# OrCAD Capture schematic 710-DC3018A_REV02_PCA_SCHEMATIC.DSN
size B; company: ANALOG DEVICES
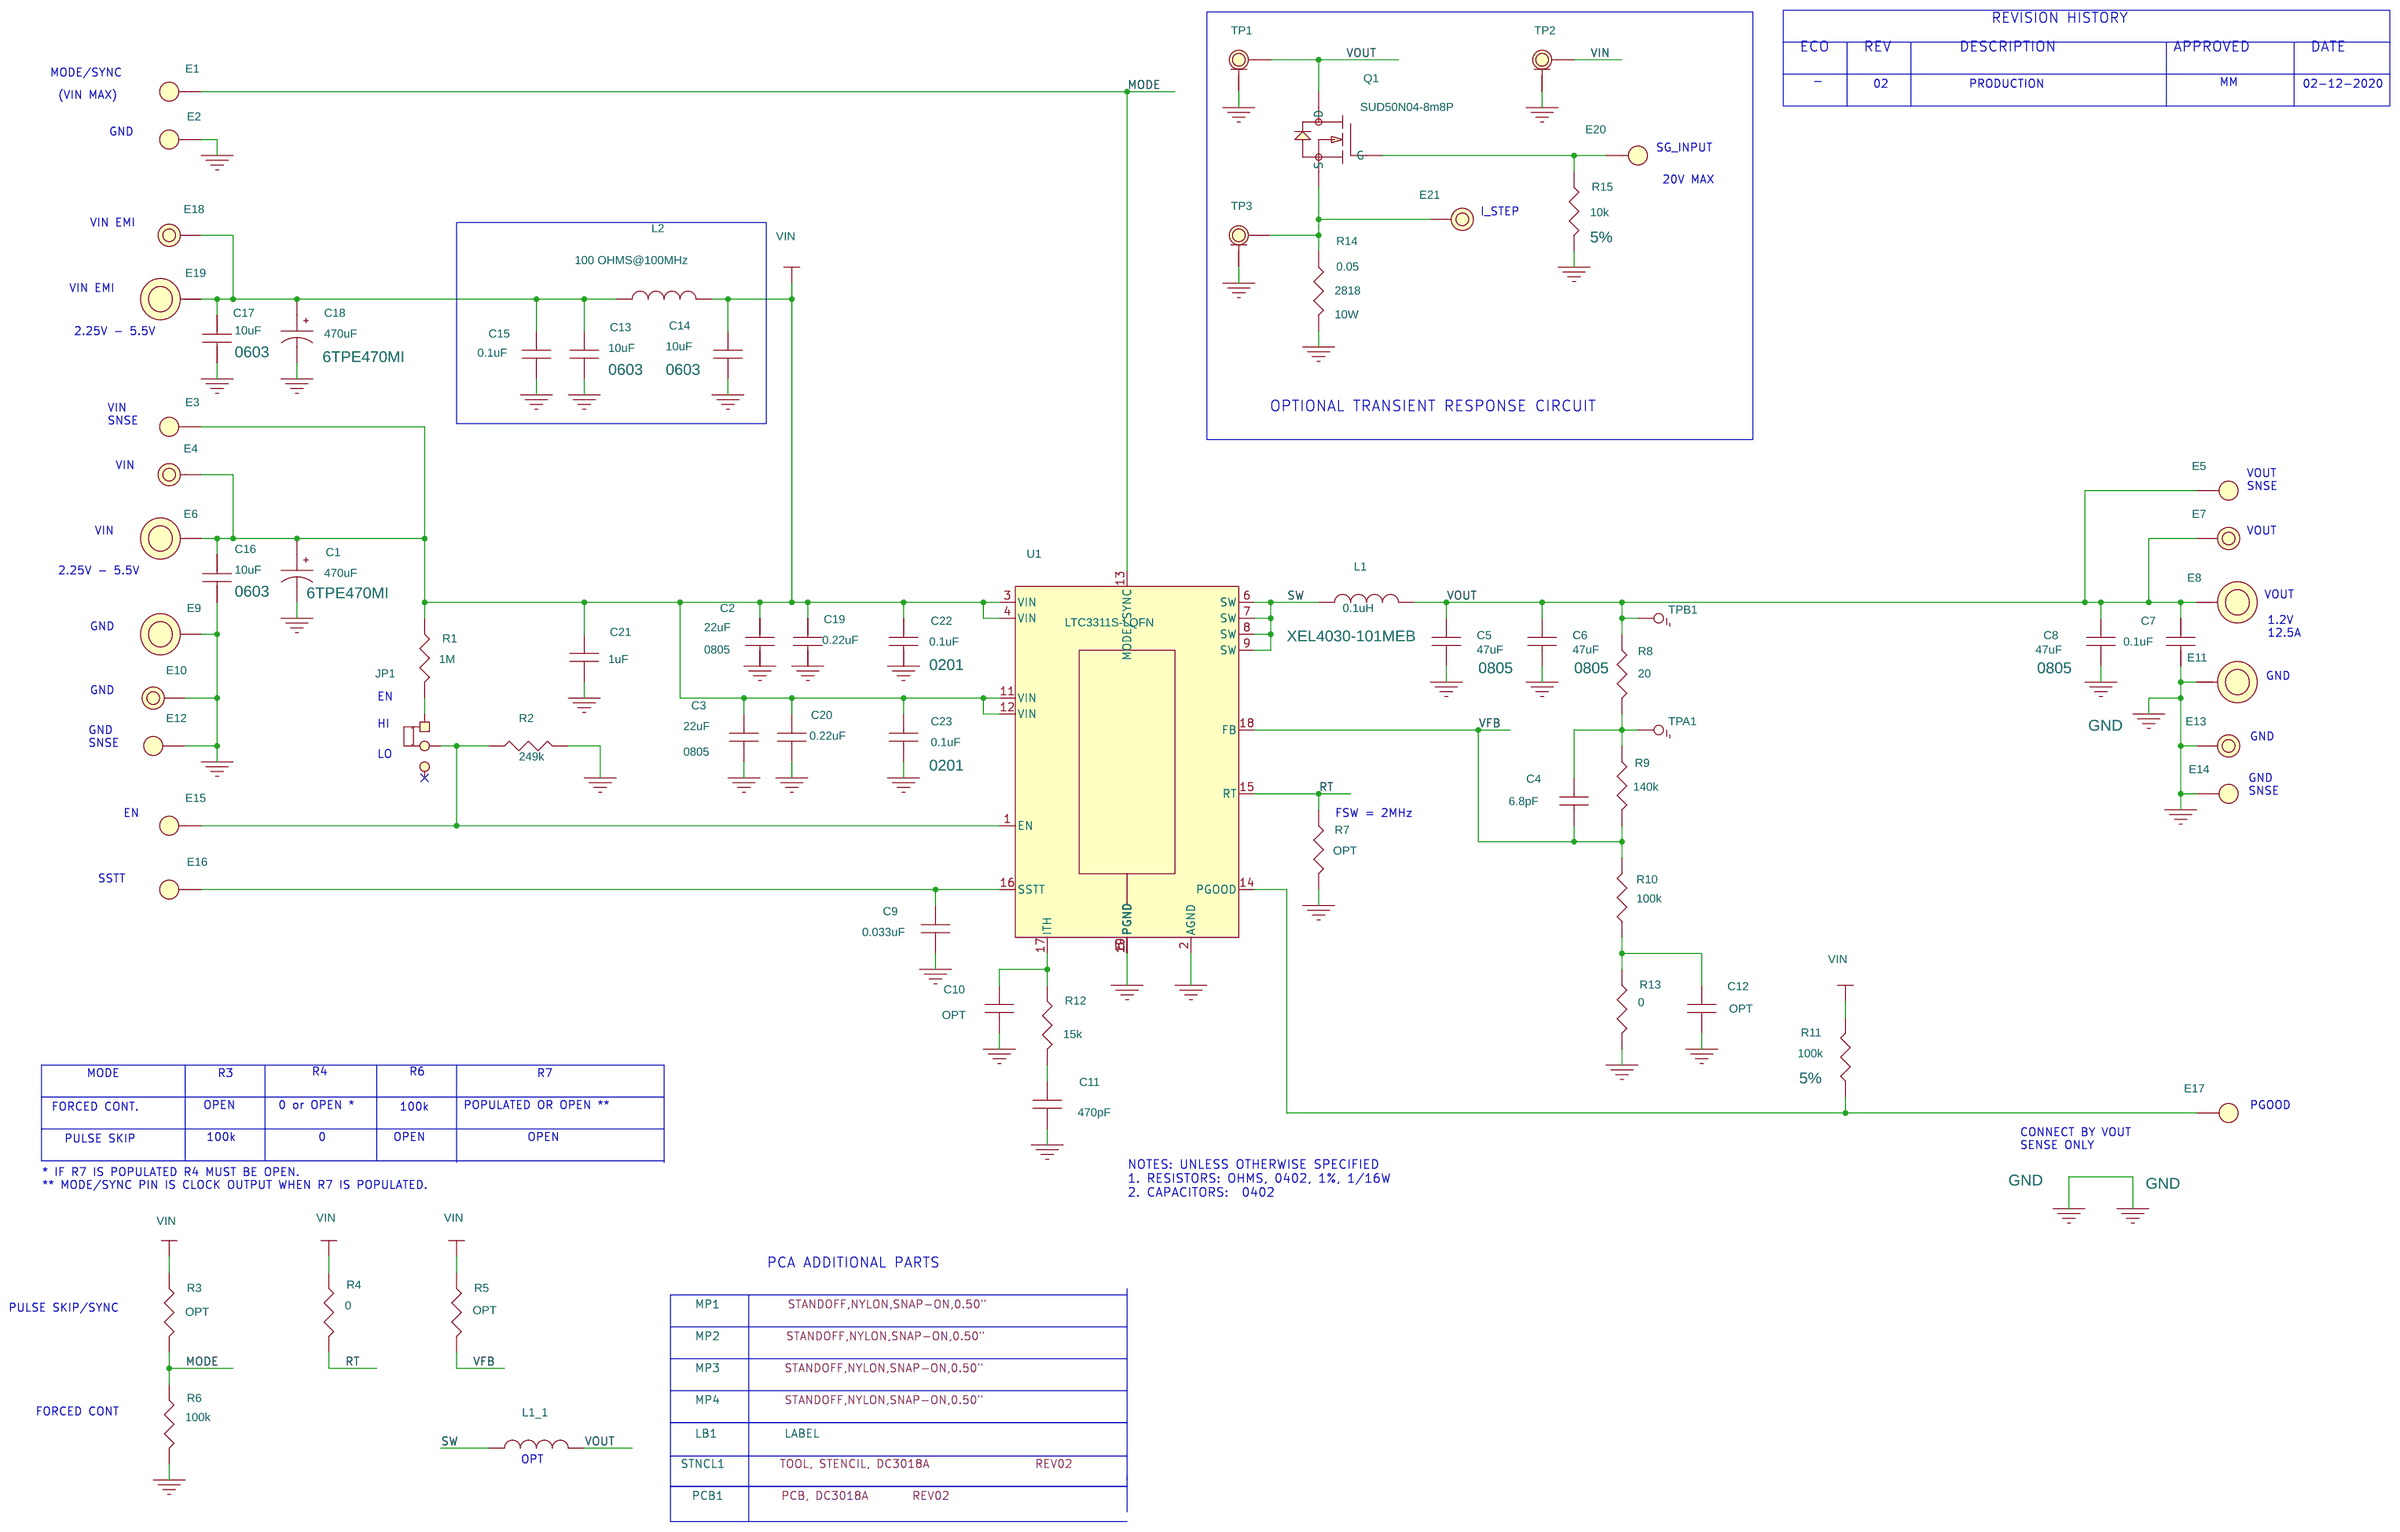
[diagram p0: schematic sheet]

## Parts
C1  470uF  [CAPMP7343N]
C2  22uF  [CC0805N]
C3  22uF  [CC0805N]
C4  6.8pF  [CC0402N]
C5  47uF  [CC0805N]
C6  47uF  [CC0805N]
C7  0.1uF  [CC0402N]
C8  47uF  [CC0805N]
C9  0.033uF  [CC0402N]
C10  OPT  [CC0402N]
C11  470pF  [CC0402N]
C12  OPT  [CC0402N]
C13  10uF  [CC0603N]
C14  10uF  [CC0603N]
C15  0.1uF  [CC0402N]
C16  10uF  [CC0603N]
C17  10uF  [CC0603N]
C18  470uF  [CAPMP7343N]
C19  0.22uF  [CC0402N]
C20  0.22uF  [CC0402N]
C21  1uF  [CC0402N]
C22  0.1uF  [CC0201M]
C23  0.1uF  [CC0201M]
E1  TEST POINT  [MILLMAX2308]
E2  TEST POINT  [MILLMAX2308]
E3  TEST POINT  [MILLMAX2308]
E4  TEST POINT  [MILLMAX2501]
E5  TEST POINT  [MILLMAX2308]
E6  BANANA JACK  [KEY-575-4]
E7  TEST POINT  [MILLMAX2501]
E8  BANANA JACK  [KEY-575-4]
E9  BANANA JACK  [KEY-575-4]
E10  TEST POINT  [MILLMAX2501]
E11  BANANA JACK  [KEY-575-4]
E12  TEST POINT  [MILLMAX2308]
E13  TEST POINT  [MILLMAX2501]
E14  TEST POINT  [MILLMAX2308]
E15  TEST POINT  [MILLMAX2308]
E16  TEST POINT  [MILLMAX2308]
E17  TEST POINT  [MILLMAX2308]
E18  TEST POINT  [MILLMAX2501]
E19  BANANA JACK  [KEY-575-4]
E20  TEST POINT  [MILLMAX2308]
E21  TEST POINT  [MILLMAX2501]
JP1  HDR  [HD1X3-079]
L1  0.1uH  [COILCRAFT-XEL4030]
L1_1  72nH  [COILCRAFT-XEL3515]
L2  100 OHMS@100MHz  [WURTH-74279226101]
LB1  LABEL  [895-0154_REV01]
MP1  STANDOFF  [KEYSTONE_8829-8834]
MP2  STANDOFF  [KEYSTONE_8829-8834]
MP3  STANDOFF  [KEYSTONE_8829-8834]
MP4  STANDOFF  [KEYSTONE_8829-8834]
PCB1  PCB, DC3018A
Q1  SUD50N04-8m8P  [TO-252-3N]
R1  1M  [CR0402N]
R2  249k  [CR0402N]
R3  OPT  [CR0402N]
R4  0  [CR0402N]
R5  OPT  [CR0402N]
R6  100k  [CR0402N]
R7  OPT  [CR0402N]
R8  20  [CR0402N]
R9  140k  [CR0402N]
R10  100k  [CR0402N]
R11  100k  [CR0402N]
R12  15k  [CR0402N]
R13  0  [CR0402N]
R14  0.05  [VISHAY-WSHP2818]
R15  10k  [CR0402N]
STNCL1  TOOL, STENCIL, DC3018A
TP1  TEST JACK  [HODEN-PA-652_ALT1]
TP2  TEST JACK  [HODEN-PA-652_ALT1]
TP3  TEST JACK  [HODEN-PA-652_ALT1]
TPA1  COPPER FEATURE PAD  [PADSTYLE1]
TPB1  COPPER FEATURE PAD  [PADSTYLE1]
U1  LTC3311S-LQFN  [LTC-LQFN-18-1548]
XJP4  SHUNT

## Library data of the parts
C1 C18 = CAP_P_ALT: CAP.,470uF,TANT,POSCAP,6.3V,20%,7343,18mOHMS,TPE; CLASS: DISCRETE; Dielectric Type: TANT,POSCAP; FPLIST: CAPMP7343N,CAPMP7343L,CAPMP7343M; Inventory Qty: 9612; Manufacturer: PANASONIC; Manufacturer PN: 6TPE470MI; PART_NUMBER: 150-0223; Package Size: 7343; Rated Voltage: 6.3V; Tolerance: 20%
C2 C3 = CAP: CAP.,22uF,X5R,25V,20%,0805; CLASS: DISCRETE; Dielectric Type: X5R; FPLIST: CC0805N,CC0805L,CC0805M; Inventory Qty: 12454; Manufacturer: AVX; Manufacturer PN: 08053D226MAT2A; PART_NUMBER: 150-0068; Package Size: 0805; Rated Voltage: 25V; Tolerance: 20%
C4 = CAP: CAP.,6.8pF,C0G,50V,+/-0.25pF,0402; CLASS: DISCRETE; Dielectric Type: C0G; FPLIST: CC0402N,CC0402L,CC0402M; Inventory Qty: 0; Manufacturer: MURATA; Manufacturer PN: GJM1555C1H6R8CB01D; PART_NUMBER: 150-2084; Package Size: 0402; Rated Voltage: 50V; Tolerance: +/-0.25pF
C5 C6 C8 = CAP: CAP.,47uF,X5R,6.3V,20%,0805,AEC-Q200; CLASS: DISCRETE; Dielectric Type: X5R; FPLIST: CC0805N,CC0805L,CC0805M; Inventory Qty: 0; Manufacturer: MURATA; Manufacturer PN: GRT21BR60J476ME13L; PART_NUMBER: 150-1208; Package Size: 0805; Rated Voltage: 6.3V; Temperature Coefficient: X5R; Tolerance: 20%
C7 C15 = CAP: CAP.,0.1uF,X5R,25V,10%,0402; CLASS: DISCRETE; Dielectric Type: X5R; FPLIST: CC0402N,CC0402L,CC0402M; Inventory Qty: 69452; Manufacturer: AVX; Manufacturer PN: 04023D104KAT2A; PART_NUMBER: 150-0249; Package Size: 0402; Rated Voltage: 25V; Tolerance: 10%
C9 = CAP: CAP.,0.033uF,X7R,25V,10%,0402; CLASS: DISCRETE; Dielectric Type: X7R; FPLIST: CC0402N,CC0402L,CC0402M; Inventory Qty: 29274; Manufacturer: KEMET; Manufacturer PN: C0402C333K3RACTU; PART_NUMBER: 150-0484; Package Size: 0402; Rated Voltage: 25V; Tolerance: 10%
C10 C12 = CAP: CAP., OPTION, 0402; CLASS: DISCRETE; PART_NUMBER: 150-3148; Package Size: 0402; Package Type: SMD
C11 = CAP: CAP.,470pF,C0G,50V,5%,0402,AEC-Q200; CLASS: DISCRETE; Dielectric Type: C0G; FPLIST: CC0402N,CC0402L,CC0402M; Inventory Qty: 0; Manufacturer: TDK; Manufacturer PN: CGA2B2C0G1H471J050BA; PART_NUMBER: 150-0632; Package Size: 0402; Rated Voltage: 50V; Tolerance: 5%
C13 C14 C16 C17 = CAP: CAP.,10uF,X5R,10V,20%,0603; CLASS: DISCRETE; Dielectric Type: X5R; Inventory Qty: 23075; Manufacturer: AVX; Manufacturer PN: 0603ZD106MAT2A; PART_NUMBER: 150-3459; Package Size: 0603; Package Type: SMD; Rated Voltage: 10V; Tolerance: 20%
C19 C20 = CAP: CAP.,0.22uF,X7R,16V,10%,0402,AEC-Q200; CLASS: DISCRETE; Dielectric Type: X7R; FPLIST: CC0402N,CC0402L,CC0402M; Inventory Qty: 29935; Manufacturer: MURATA; Manufacturer PN: GCM155R71C224KE02D; PART_NUMBER: 150-0508; Package Size: 0402; Rated Voltage: 16V; Tolerance: 10%
C21 = CAP: CAP.,1uF,X5R,10V,20%,0402; CLASS: DISCRETE; Dielectric Type: X5R; FPLIST: CC0402N,CC0402L,CC0402M; Inventory Qty: 29600; Manufacturer: MURATA; Manufacturer PN: GRM153R61A105ME95D; PART_NUMBER: 150-0257; Package Size: 0402; Rated Voltage: 10V; Tolerance: 20%
C22 C23 = CAP: CAP.,0.1uF,X7S,16V,10%,0201; CLASS: DISCRETE; Dielectric Type: X7S; FPLIST: CC0201N,CC0201L,CC0201M; Inventory Qty: 30000; Manufacturer: MURATA; Manufacturer PN: GRM033C71C104KE14D; PART_NUMBER: 150-0807; Package Size: 0201; Rated Voltage: 16V; Temperature Coefficient: X7S; Tolerance: 10%
E1-E3 E5 E12 E14-E17 E20 = TEST_POINT_.156_MILL-MAX_2308: TEST POINT,TURRET,0.064" MTG. HOLE,PCB 0.062" THK; CLASS: IO; Inventory Qty: 682175; Manufacturer PN: 2308-2-00-80-00-00-07-0; PART_NUMBER: 260-0004
E4 E7 E10 E13 E18 = TESTPOINT_.219_MILL-MAX_2501: TEST POINT,TURRET,0.094" MTG. HOLE,PCB 0.062" THK; CLASS: IO; Inventory Qty: 372625; Manufacturer: MILL-MAX; Manufacturer PN: 2501-2-00-80-00-00-07-0; PART_NUMBER: 260-0003
E6 E8 E9 E11 E19 = BANANA_KEYSTONE-575-4: CONN.,BANANA JACK,FEMALE,THT,NON-INSULATED,SWAGE,0.218"; CLASS: IO; Inventory Qty: 169522; Manufacturer: KEYSTONE; Manufacturer PN: 575-4; PART_NUMBER: 250-0428
E21 = TESTPOINT_.219_MILL-MAX_2501: TEST POINT,TURRET,0.094" MTG. HOLE,PCB 0.062" THK; CLASS: IO; FPLIST: MILLMAX2501,MILLMAX2501_ALT1; Inventory Qty: 372625; Manufacturer: MILL-MAX; Manufacturer PN: 2501-2-00-80-00-00-07-0; PART_NUMBER: 260-0003
JP1 = 3_PIN_HEADER_.079_SINGLE_ROW_D: CONN.,HDR,MALE,1x3,2mm,VERT,ST,THT; CLASS: IO; Inventory Qty: 24592; Manufacturer: Wurth Elektronik; Manufacturer PN: 62000311121; PART_NUMBER: 250-0484
L1 = IND_ALT: IND.,0.1uH,PWR,SHIELDED,20%,25.8A,1.8mOhms,4.3x4.3mm,XEL4030,AEC-Q200; CLASS: DISCRETE; Inventory Qty: 2550; Manufacturer: COILCRAFT; Manufacturer PN: XEL4030-101MEB; PART_NUMBER: 200-0670; Package Size: 4.3x4.3mm,XEL4030; Tolerance: 20%
L1_1 = IND_ALT: IND.,72nH,PWR,20%,23.6A,3.15mOHMS,3.2mmX3.5mm,AEC-Q200; CLASS: DISCRETE; Inventory Qty: 1392; Manufacturer: Coilcraft; Manufacturer PN: XEL3515-720MEB; PART_NUMBER: 200-0450; Package Size: 3.2mmX3.5mm; Tolerance: 20%
L2 = IND_ALT: IND.,100 OHMS@100MHz,FERRITE BEAD,25%,8A,6mOHMS,1812; CLASS: DISCRETE; Inventory Qty: 2492; Manufacturer: WURTH ELEKTRONIK; Manufacturer PN: 74279226101; PART_NUMBER: 200-0280; Package Size: 1812; Tolerance: 25%
LB1 = BLANK_LABEL: LABEL SPEC, DEMO BOARD SERIAL NUMBER; Inventory Qty: 0; Manufacturer: BRADY; Manufacturer PN: THT-96-717-10; PART_NUMBER: 895-0154
MP1-MP4 = BLANK_MECHANICAL_PART: STANDOFF,NYLON,SNAP-ON,0.50"; CLASS: DISCRETE; FPLIST: KEYSTONE_8829-8834,MTG-8831; Inventory Qty: 176342; Manufacturer: KEYSTONE; Manufacturer PN: 8833; PART_NUMBER: 763-0007
PCB1 = BLANK_PCB_PART: BOM Notes: REV02; CLASS: DISCRETE; Inventory Qty: 0; Manufacturer: EAGLE TECH. INC.; Manufacturer PN: 600-DC3018A; PART_NUMBER: 600-DC3018A
Q1 = 3P_N-CH_TYPE2A: XSTR.,MOSFET,N-CH,40V,14A,DPAK (TO-252); CLASS: DISCRETE; FPLIST: TO-252-3N,TO-252-3L,TO-252-3M; Inventory Qty: 40938; Manufacturer: VISHAY; Manufacturer PN: SUD50N04-8M8P-4GE3; PART_NUMBER: 240-0021; Package Type: DPAK (TO-252); Rated Voltage: 40V
R1 = RES: RES.,1M OHMS,1%,1/16W,0402,AEC-Q200; CLASS: DISCRETE; FPLIST: CR0402N,CR0402L,CR0402M; Inventory Qty: 90169; Manufacturer: STACKPOLE ELECTRONICS, INC.; Manufacturer PN: RMCF0402FT1M00; PART_NUMBER: 100-2457; Package Size: 0402; Rated Power: 1/16W; Temperature Coefficient: 100ppm; Tolerance: 1%
R2 = RES: RES.,249k OHMS,1%,1/16W,0402,AEC-Q200; CLASS: DISCRETE; FPLIST: CR0402N,CR0402L,CR0402M; Inventory Qty: 28050; Manufacturer: NIC; Manufacturer PN: NRC04F2493TRF; PART_NUMBER: 100-2663; Package Size: 0402; Rated Power: 1/16W; Temperature Coefficient: 100ppm; Tolerance: 1%
R3 R5 R7 = RES: RES., OPTION, 0402; CLASS: DISCRETE; FPLIST: CR0402N,CR0402L,CR0402M; PART_NUMBER: 100-0357; Package Size: 0402
R4 R13 = RES: RES.,0 OHM,1/16W,0402,AEC-Q200; CLASS: DISCRETE; FPLIST: CR0402N,CR0402L,CR0402M; Inventory Qty: 110814; Manufacturer: NIC; Manufacturer PN: NRC04ZOTRF; PART_NUMBER: 100-2023; Package Size: 0402; Rated Power: 1/16W
R6 R11 = RES: RES.,100k OHMS,5%,1/16W,0402,AEC-Q200; CLASS: DISCRETE; FPLIST: CR0402N,CR0402L,CR0402M; Inventory Qty: 44356; Manufacturer: NIC; Manufacturer PN: NRC04J104TRF; PART_NUMBER: 100-0359; Package Size: 0402; Rated Power: 1/16W; Temperature Coefficient: 200ppm/C; Tolerance: 5%
R8 = RES: RES.,20 OHMS,1%,1/16W,0402,AEC-Q200; CLASS: DISCRETE; FPLIST: CR0402N,CR0402L,CR0402M; Inventory Qty: 32382; Manufacturer: NIC; Manufacturer PN: NRC04F20R0TRF; PART_NUMBER: 100-0250; Package Size: 0402; Rated Power: 1/16W; Temperature Coefficient: 100ppm; Tolerance: 1%
R9 = RES: RES.,140k OHMS,1%,1/16W,0402,AEC-Q200; CLASS: DISCRETE; FPLIST: CR0402N,CR0402L,CR0402M; Inventory Qty: 71764; Manufacturer: NIC; Manufacturer PN: NRC04F1403TRF; PART_NUMBER: 100-2880; Package Size: 0402; Rated Power: 1/16W; Temperature Coefficient: 100ppm; Tolerance: 1%
R10 = RES: RES.,100k OHMS,1%,1/16W,0402,AEC-Q200; CLASS: DISCRETE; FPLIST: CR0402N,CR0402L,CR0402M; Inventory Qty: 153378; Manufacturer: VISHAY; Manufacturer PN: CRCW0402100KFKED; PART_NUMBER: 100-2396; Package Size: 0402; Rated Power: 1/16W; Temperature Coefficient: 100ppm; Tolerance: 1%
R12 = RES: RES.,15k OHMS,1%,1/16W,0402; CLASS: DISCRETE; FPLIST: CR0402N,CR0402L,CR0402M; Inventory Qty: 41183; Manufacturer: NIC; Manufacturer PN: NRC04F1502TRF; PART_NUMBER: 100-2315; Package Size: 0402; Rated Power: 1/16W; Temperature Coefficient: 100ppm/C; Tolerance: 1%
R14 = RES: RES.,0.05 OHMS,1%,10W,2818,AEC-Q200,METAL,HP; CLASS: DISCRETE; Inventory Qty: 0; Manufacturer: VISHAY; Manufacturer PN: WSHP2818R0500FEA; PART_NUMBER: 100-1684; Package Size: 2818; Rated Power: 10W; Temperature Coefficient: +/-75ppm; Tolerance: 1%
R15 = RES: RES.,10k OHMS,5%,1/16W,0402,AEC-Q200; CLASS: DISCRETE; Inventory Qty: 69954; Manufacturer: NIC; Manufacturer PN: NRC04J103TRF; PART_NUMBER: 100-0214; Package Size: 0402; Rated Power: 1/16W; Temperature Coefficient: 200ppm; Tolerance: 5%
STNCL1 = BLANK_STENCIL_PART: BOM Notes: REV02; CLASS: DISCRETE; Inventory Qty: 0; Manufacturer: ANALOG DEVICES; Manufacturer PN: 830-DC3018A; PART_NUMBER: 830-DC3018A
TP1-TP3 = HODEN_TEST_JACK_PK5-2.5MM-113_1: CONN.,TEST JACK,PLUG,VERT. THT,SHIELDED, 1 POS; CLASS: IO; FPLIST: HODEN-PA-652, HODEN-PA-652_ALT1; Manufacturer: HODEN ELECTRONICS CO; Manufacturer PN: PK5-2.5MM-113; PART_NUMBER: TMP-3717
TPA1 TPB1 = PAD_SMALL_FILLED: TESTPOINT, PCB COPPER FEATURE; CLASS: IO; Manufacturer: N/A; Manufacturer PN: N/A; PART_NUMBER: PCBPADS-11
U1 = LTC3311S-LQFN: IC,Low Voltage Syn. Step-Down Reg,LQFN-18; CLASS: IC; Inventory Qty: 0; Manufacturer: ANALOG DEVICES; Manufacturer PN: LTC3311SEV#PBF; PART_NUMBER: LTC3311SEV#PBF; Package Size: 18-LQFN; Package Type: LQFN-18
XJP4 = CONN_SHUNT_2_POS_2mm: CONN.,SHUNT,FEMALE,2 POS,2mm; CLASS: IO; Inventory Qty: 70216; Manufacturer: Wurth Elektronik; Manufacturer PN: 60800213421; PART_NUMBER: 250-0485

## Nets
GND: C1.2 C2.2 C3.2 C5.2 C6.2 C7.2 C8.2 C9.2 C10.2 C11.2 C12.2 C13.2 C14.2 C15.2 C16.2 C17.2 C18.2 C19.2 C20.2 C21.2 C22.2 C23.2 E2.1(A) E9.1 E10.1 E11.1 E12.1(A) E13.1 E14.1(A) R2.2 R6.2 R7.2 R13.2 R14.2 R15.2 TP1.2(GND) TP1.3(GND) TP1.4(GND) TP1.5(GND) TP2.2(GND) TP2.3(GND) TP2.4(GND) TP2.5(GND) TP3.2(GND) TP3.3(GND) TP3.4(GND) TP3.5(GND) U1.2(AGND) U1.5(PGND) U1.10(PGND) U1.19(PGND)
VIN: C1.1 C2.1 C3.1 C14.1 C16.1 C19.1 C20.1 C21.1 C22.1 C23.1 E3.1(A) E4.1 E6.1 L2.2 R1.1 R3.1 R4.1 R5.1 R11.1 TP2.1 U1.3(VIN) U1.4(VIN) U1.11(VIN) U1.12(VIN)
MODE: E1.1(A) R3.2 R6.1 U1.13(MODE/SYNC)
RT: R4.2 R7.1 U1.15(RT)
SW: L1.1 L1_1.1 U1.6(SW) U1.7(SW) U1.8(SW) U1.9(SW)
VFB: C4.2 R5.2 R9.2 R10.2 U1.18(FB)
VOUT: C5.1 C6.1 C7.1 C8.1 E5.1(A) E7.1 E8.1 L1.2 L1_1.2 Q1.2(D) R8.1 TP1.1 TPB1.1
N16777546: E15.1(A) JP1.2 R2.1 U1.1(EN)
N16777612: C4.1 R8.2 R9.1 TPA1.1
N16777634: C12.1 R10.1 R13.1
N16777640: E17.1(A) R11.2 U1.14(PGOOD)
N16777648: C10.1 R12.1 U1.17(ITH)
N16777650: C11.1 R12.2
N16777742: JP1.1 R1.2
N16777770: C9.1 E16.1(A) U1.16(SSTT)
N16814255: C13.1 C15.1 C17.1 C18.1 E18.1 E19.1 L2.1
N16841248: E20.1(A) Q1.1(G) R15.1
N16841255: E21.1 Q1.3(S) R14.1 TP3.1

Not connected (* = marked no-connect by the designer): JP1 3*

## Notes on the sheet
- REVISION HISTORY
- ECO
- REV
- DESCRIPTION
- APPROVED
- DATE
- MODE/SYNC
- -
- MM
- (VIN MAX)
- 02
- PRODUCTION
- 02-12-2020
- GND
- SG_INPUT
- 20V MAX
- I_STEP
- VIN EMI
- VIN EMI
- 2.25V - 5.5V
- VIN
  SNSE
- OPTIONAL TRANSIENT RESPONSE CIRCUIT
- VIN
- VOUT
  SNSE
- VIN
- VOUT
- 2.25V - 5.5V
- VOUT
- GND
- 1.2V
  12.5A
- GND
- GND
- EN
- GND
  SNSE
- HI
- GND
- LO
- GND
  SNSE
- EN
- FSW = 2MHz
- SSTT
- MODE
- R3
- R4
- R6
- R7
- FORCED CONT.
- OPEN
- 0 or OPEN *
- 100k
- POPULATED OR OPEN **
- PGOOD
- 100k
- 0
- OPEN
- OPEN
- CONNECT BY VOUT
  SENSE ONLY
- PULSE SKIP
- * IF R7 IS POPULATED R4 MUST BE OPEN.
  ** MODE/SYNC PIN IS CLOCK OUTPUT WHEN R7 IS POPULATED.
- NOTES: UNLESS OTHERWISE SPECIFIED
  1. RESISTORS: OHMS, 0402, 1%, 1/16W
  2. CAPACITORS:  0402
- PCA ADDITIONAL PARTS
- PULSE SKIP/SYNC
- FORCED CONT
- OPT
